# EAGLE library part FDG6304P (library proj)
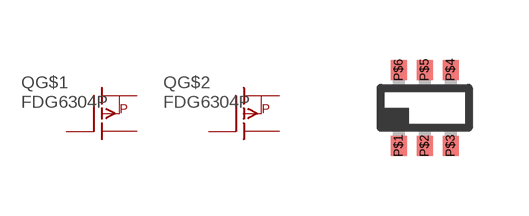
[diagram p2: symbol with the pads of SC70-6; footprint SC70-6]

Designator prefix Q; gates G$1=FET-DUAL-P G$2=FET-DUAL-P

## FDG6304P  [SC70-6]
P$1  G$1:SP  pas
P$2  G$1:GP  pas
P$3  G$2:DP  pas
P$4  G$2:SP  pas
P$5  G$2:GP  pas
P$6  G$1:DP  pas

## Footprint SC70-6 (pad centres in mm)
Fairchild SC70-6
smd 0.4 x 0.5: P$1 -0.65,-0.95; P$2 0,-0.95; P$3 0.65,-0.95; P$4 0.65,0.95; P$5 0,0.95; P$6 -0.65,0.95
